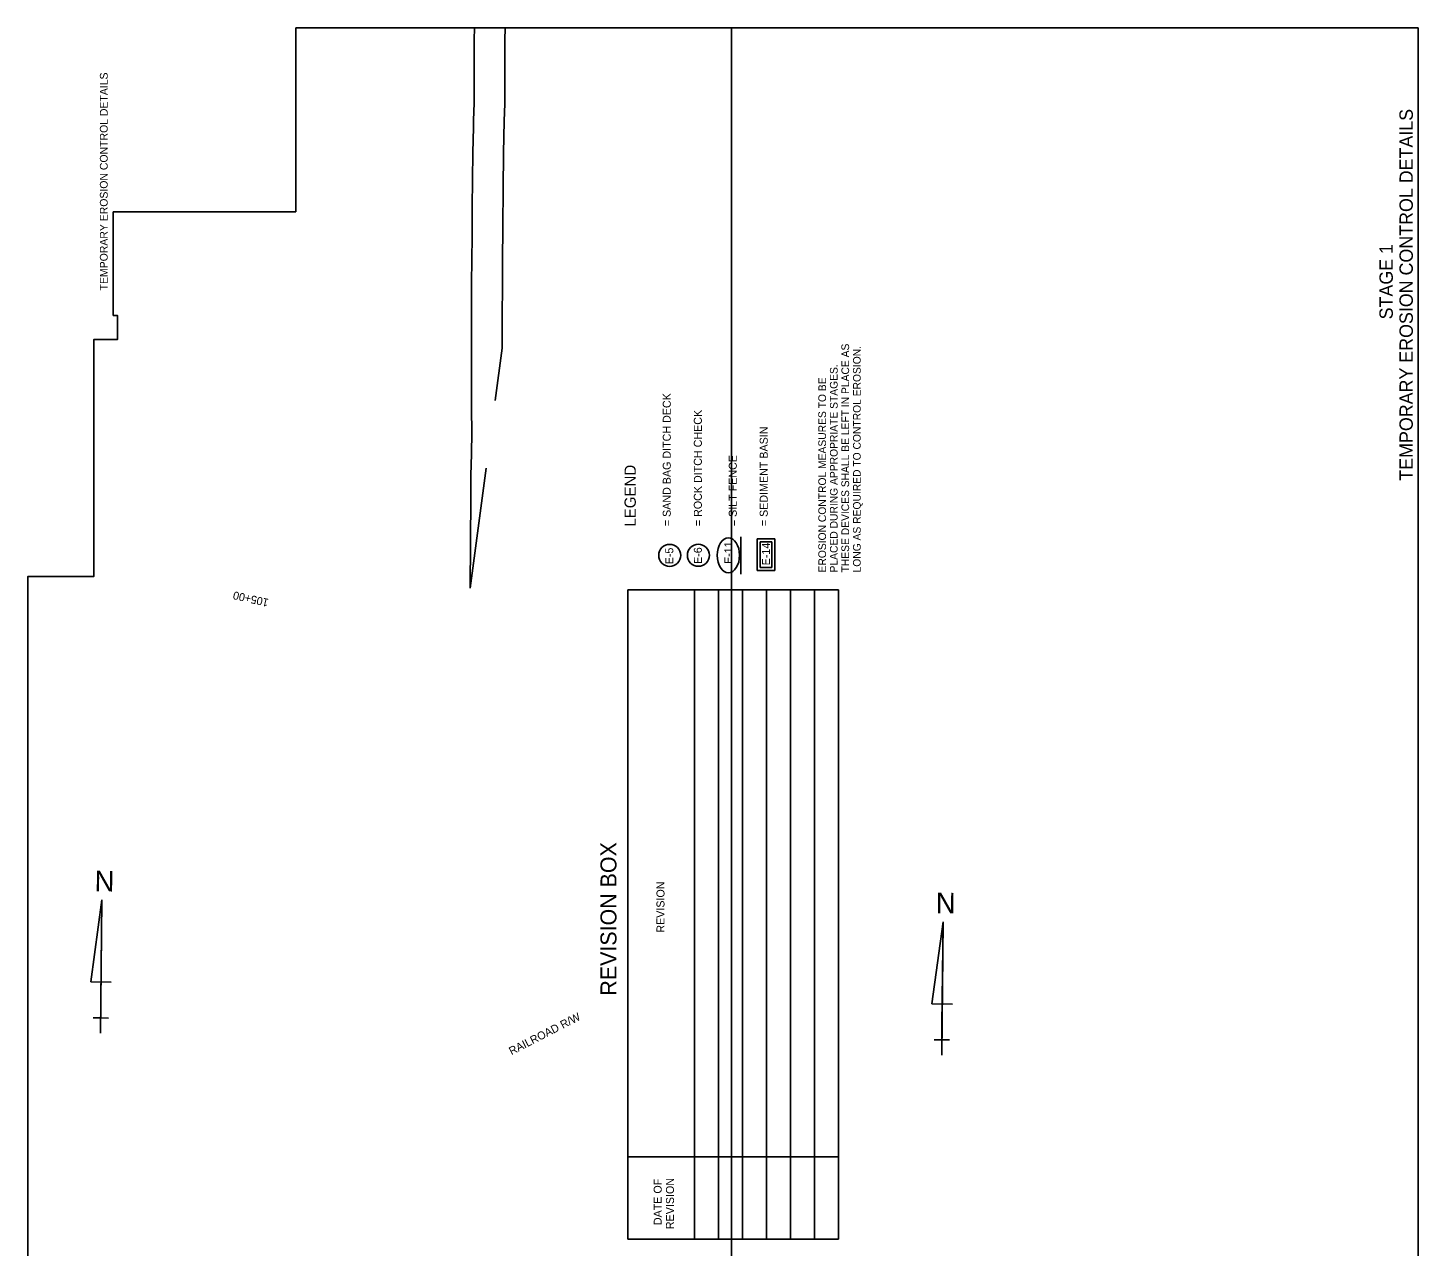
# Model space of a CAD drawing. Extents: x 1712161 to 1713203, y 549259 to 550855.
# Drawn here: x 1712161 to 1713203, y 549941 to 550855 of the extents above; entities that cross this region are included whole.
import ezdxf

# ---------------------------------------------------------------- set-up
doc = ezdxf.new("R2010")
doc.units = 0
for name, color, linetype in [('Default', 7, 'Continuous'), ('R_Border', 7, 'Continuous'), ('R_Contours', 7, 'Continuous'), ('R_Horz Alg', 7, 'Continuous'), ('R_Horz Alg Annot', 7, 'Continuous'), ('R_Proposed Const Limits_Fill', 7, 'Continuous')]:
    doc.layers.add(name, color=color, linetype=linetype)

msp = doc.modelspace()

# ---------------------------------------------------------------- linework, layer by layer
at = {"layer": 'Default'}
for points in [[(1712361.5, 550854.5), (1712688.2, 550854.5), (1712688.2, 549259.2), (1712160.6, 549259.2), (1712160.6, 550443.2), (1712210, 550443.2), (1712210, 550620.8), (1712227.8, 550620.8), (1712227.8, 550639), (1712224.6, 550639), (1712224.6, 550716.7)], [(1712361.5, 550854.5), (1712688.2, 550854.5), (1712688.2, 549259.2), (1712160.6, 549259.2), (1712160.6, 550443.2), (1712210, 550443.2), (1712210, 550620.8), (1712227.8, 550620.8), (1712227.8, 550639), (1712224.6, 550639), (1712224.6, 550716.7)], [(1712361.5, 550854.5), (1712688.2, 550854.5), (1712688.2, 549259.2), (1712160.6, 549259.2), (1712160.6, 550443.2), (1712210, 550443.2), (1712210, 550620.8), (1712227.8, 550620.8), (1712227.8, 550639), (1712224.6, 550639), (1712224.6, 550716.7)], [(1712361.5, 550854.5), (1712688.2, 550854.5), (1712688.2, 549259.2), (1712160.6, 549259.2), (1712160.6, 550443.2), (1712210, 550443.2), (1712210, 550620.8), (1712227.8, 550620.8), (1712227.8, 550639), (1712224.6, 550639), (1712224.6, 550716.7)], [(1712361.5, 550854.5), (1712688.2, 550854.5), (1712688.2, 549259.2), (1712160.6, 549259.2), (1712160.6, 550443.2), (1712210, 550443.2), (1712210, 550620.8), (1712227.8, 550620.8), (1712227.8, 550639), (1712224.6, 550639), (1712224.6, 550716.7)], [(1712361.5, 550854.5), (1712688.2, 550854.5), (1712688.2, 549259.2), (1712160.6, 549259.2), (1712160.6, 550443.2), (1712210, 550443.2), (1712210, 550620.8), (1712227.8, 550620.8), (1712227.8, 550639), (1712224.6, 550639), (1712224.6, 550716.7)], [(1712361.5, 550854.5), (1712688.2, 550854.5), (1712688.2, 549259.2), (1712160.6, 549259.2), (1712160.6, 550443.2), (1712210, 550443.2), (1712210, 550620.8), (1712227.8, 550620.8), (1712227.8, 550639), (1712224.6, 550639), (1712224.6, 550716.7)], [(1712361.5, 550854.5), (1712688.2, 550854.5), (1712688.2, 549259.2), (1712160.6, 549259.2), (1712160.6, 550443.2), (1712210, 550443.2), (1712210, 550620.8), (1712227.8, 550620.8), (1712227.8, 550639), (1712224.6, 550639), (1712224.6, 550716.7)], [(1712224.6, 550716.7), (1712361.5, 550716.7), (1712361.5, 550854.5)], [(1712224.6, 550716.7), (1712361.5, 550716.7), (1712361.5, 550854.5)], [(1712224.6, 550716.7), (1712361.5, 550716.7), (1712361.5, 550854.5)], [(1712224.6, 550716.7), (1712361.5, 550716.7), (1712361.5, 550854.5)], [(1712224.6, 550716.7), (1712361.5, 550716.7), (1712361.5, 550854.5)], [(1712224.6, 550716.7), (1712361.5, 550716.7), (1712361.5, 550854.5)], [(1712224.6, 550716.7), (1712361.5, 550716.7), (1712361.5, 550854.5)], [(1712224.6, 550716.7), (1712361.5, 550716.7), (1712361.5, 550854.5)]]:
    msp.add_lwpolyline(points, dxfattribs=at)
msp.add_lwpolyline([(1712688.2, 549259.2), (1712688.2, 550854.5), (1713202.9, 550854.5), (1713202.9, 549259.2)], close=True, dxfattribs=at)
msp.add_lwpolyline([(1712688.2, 549259.2), (1712688.2, 550854.5), (1713202.9, 550854.5), (1713202.9, 549259.2)], close=True, dxfattribs=at)
msp.add_lwpolyline([(1712688.2, 549259.2), (1712688.2, 550854.5), (1713202.9, 550854.5), (1713202.9, 549259.2)], close=True, dxfattribs=at)
msp.add_lwpolyline([(1712688.2, 549259.2), (1712688.2, 550854.5), (1713202.9, 550854.5), (1713202.9, 549259.2)], close=True, dxfattribs=at)
msp.add_lwpolyline([(1712688.2, 549259.2), (1712688.2, 550854.5), (1713202.9, 550854.5), (1713202.9, 549259.2)], close=True, dxfattribs=at)
msp.add_lwpolyline([(1712688.2, 549259.2), (1712688.2, 550854.5), (1713202.9, 550854.5), (1713202.9, 549259.2)], close=True, dxfattribs=at)
at = {"layer": 'R_Contours'}
for p, q in [((1712510.9, 550575.3), (1712516.1, 550614.5)), ((1712492.1, 550434.5), (1712504.1, 550524.5))]:
    msp.add_line(p, q, dxfattribs=at)
for points in [[(1712495.5, 550854.5), (1712495.3, 550845.5), (1712495.2, 550821.9), (1712495.1, 550798.3), (1712494.7, 550785.1), (1712494.6, 550779.9), (1712494.3, 550761.1), (1712494, 550740.6), (1712493.8, 550720.1), (1712493.6, 550699.6), (1712493.4, 550679), (1712493.3, 550664.5), (1712493.2, 550650), (1712493.2, 550635.6), (1712493.1, 550621.1), (1712493.2, 550603.6), (1712493.2, 550586.2), (1712493.3, 550568.8), (1712493.4, 550551.4), (1712493.1, 550535.2), (1712492.8, 550519), (1712492.6, 550502.7), (1712492.1, 550434.5)], [(1712516.1, 550614.5), (1712516.1, 550621), (1712516.4, 550678.9), (1712517.3, 550760.8), (1712517.7, 550784.5), (1712518.1, 550797.8), (1712518.3, 550845.3), (1712518.5, 550854.5)]]:
    msp.add_lwpolyline(points, dxfattribs=at)
at = {"layer": 'R_Horz Alg'}
for p, q in [((1712216.2, 550200.9), (1712207.8, 550139.4)), ((1712215.1, 550100.9), (1712216.2, 550200.9)), ((1712216.2, 550200.9), (1712215.4, 550123.9)), ((1712846.8, 550184.4), (1712838.4, 550123)), ((1712845.7, 550084.4), (1712846.8, 550184.4)), ((1712846.8, 550184.4), (1712845.9, 550107.5)), ((1712207.8, 550139.4), (1712223.2, 550139.2)), ((1712215.1, 550100.9), (1712215.4, 550123.9)), ((1712838.4, 550123), (1712853.8, 550122.8)), ((1712215.2, 550112.4), (1712209.5, 550112.5)), ((1712209.5, 550112.5), (1712221, 550112.3)), ((1712215.1, 550100.9), (1712215.2, 550112.4)), ((1712845.7, 550084.4), (1712845.9, 550107.5)), ((1712845.8, 550096), (1712840, 550096)), ((1712840, 550096), (1712851.6, 550095.9)), ((1712845.7, 550084.4), (1712845.8, 550096))]:
    msp.add_line(p, q, dxfattribs=at)
at = {"layer": 'R_Horz Alg Annot'}
for p, q in [((1712688.2, 550643.9), (1712688.2, 550854.5)), ((1712688.2, 550433.3), (1712688.2, 550440.6)), ((1712610.4, 549946.5), (1712610.4, 550433.3)), ((1712610.4, 550433.3), (1712768.4, 550433.3)), ((1712660.4, 549946.5), (1712660.4, 550433.3)), ((1712678.4, 549946.5), (1712678.4, 550433.3)), ((1712696.4, 549946.5), (1712696.4, 550433.3)), ((1712714.4, 549946.5), (1712714.4, 550433.3)), ((1712732.4, 549946.5), (1712732.4, 550433.3)), ((1712750.4, 549946.5), (1712750.4, 550433.3)), ((1712768.4, 549946.5), (1712768.4, 550433.3)), ((1712610.4, 550008.3), (1712768.4, 550008.3)), ((1712610.4, 549946.5), (1712768.4, 549946.5)), ((1712688.2, 549755.8), (1712688.2, 549946.5))]:
    msp.add_line(p, q, dxfattribs=at)
at = {"layer": 'R_Proposed Const Limits_Fill'}
for p, q in [((1712707.4, 550471.5), (1712720.6, 550471.5)), ((1712707.4, 550447.8), (1712707.4, 550471.5)), ((1712709.6, 550450), (1712709.6, 550469.2)), ((1712709.6, 550469.2), (1712718.3, 550469.2)), ((1712718.3, 550450), (1712718.3, 550469.2)), ((1712720.6, 550447.8), (1712720.6, 550471.5)), ((1712709.6, 550450), (1712718.3, 550450)), ((1712707.4, 550447.8), (1712720.6, 550447.8))]:
    msp.add_line(p, q, dxfattribs=at)
msp.add_lwpolyline([(1712695.2, 550445.1), (1712695.2, 550472.9)], dxfattribs=at)
for centre in [(1712641.8, 550459.1), (1712663.3, 550459.2)]:
    msp.add_circle(centre, 8.26, dxfattribs=at)
msp.add_ellipse((1712685.8, 550459.2), major_axis=(0, 13.1), ratio=0.638788, dxfattribs=at)

# ---------------------------------------------------------------- texts
at = {"layer": 'R_Border'}
msp.add_text('TEMPORARY EROSION CONTROL DETAILS', height=5.862, rotation=90, dxfattribs=at).set_placement((1712220.5, 550657.7))
at = {"layer": 'R_Horz Alg'}
for p in [(1712210.6, 550207.3), (1712841.2, 550190.9)]:
    msp.add_text('N', height=15.4, rotation=359.3683, dxfattribs=at).set_placement(p)
at = {"layer": 'R_Horz Alg Annot'}
for s, height, rotation, p in [('TEMPORARY EROSION CONTROL DETAILS', 10, 90, (1713198.9, 550515.1)), ('STAGE 1', 10, 90, (1713183.9, 550636)), ('105+00', 6, 167.2066, (1712341.6, 550426.3)), ('REVISION BOX', 12, 90, (1712601.9, 550129.1)), ('REVISION', 6, 90, (1712637.9, 550176.3)), ('RAILROAD R/W', 6, 27.2066, (1712523.2, 550084.4)), ('DATE OF', 6, 90, (1712635.8, 549957.1)), ('REVISION', 6, 90, (1712645, 549954.1))]:
    msp.add_text(s, height=height, rotation=rotation, dxfattribs=at).set_placement(p)
at = {"layer": 'R_Proposed Const Limits_Fill'}
for s, height, rotation, p in [('THESE DEVICES SHALL BE LEFT IN PLACE AS ', 5.769, 90, (1712776.3, 550446.3)), ('LONG AS REQUIRED TO CONTROL EROSION.', 5.769, 90, (1712785, 550446.3)), ('PLACED DURING APPROPRIATE STAGES. ', 5.769, 90, (1712767.7, 550446.3)), ('EROSION CONTROL MEASURES TO BE', 5.769, 90, (1712759, 550446.3)), ('= SAND BAG DITCH DECK', 6, 90, (1712642.6, 550481)), ('= ROCK DITCH CHECK', 6, 90, (1712665.9, 550481)), ('= SEDIMENT BASIN', 6, 90, (1712715.3, 550481)), ('= SILT FENCE', 6, 90, (1712692.1, 550481)), ('LEGEND', 8.44, 90, (1712616.4, 550480.6)), ('E-11', 6, 90.2144, (1712688.8, 550452.7)), ('E-5 ', 6, 90, (1712644.5, 550452.4)), ('E-6 ', 6, 90.4005, (1712666, 550452.7)), ('E-14', 6, 89.9884, (1712717, 550451.6))]:
    msp.add_text(s, height=height, rotation=rotation, dxfattribs=at).set_placement(p)

doc.saveas('drawing.dxf')
